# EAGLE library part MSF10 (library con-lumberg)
MSF CONNECTOR
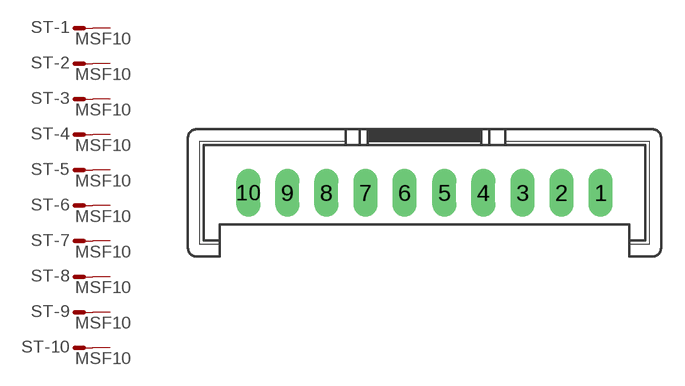
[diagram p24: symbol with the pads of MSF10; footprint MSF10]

Designator prefix ST; gates -1=M -2=M -3=M -4=M -5=M -6=M -7=M -8=M -9=M -10=M

## MSF10 (MPN: 2,5 MSF 10; OC_FARNELL: 1212155; OC_NEWARK: 96K6056)  [MSF10]
1  -1:S  pas
2  -2:S  pas
3  -3:S  pas
4  -4:S  pas
5  -5:S  pas
6  -6:S  pas
7  -7:S  pas
8  -8:S  pas
9  -9:S  pas
10  -10:S  pas

## Footprint MSF10 (pad centres in mm)
MSF CONNECTOR Buerklin Nr. 56 F 562
drill 1.016 long: 1 11.252,-2.54; 2 8.763,-2.54; 3 6.274,-2.54; 4 3.759,-2.54; 5 1.27,-2.54; 6 -1.27,-2.54; 7 -3.759,-2.54; 8 -6.274,-2.54; 9 -8.763,-2.54; 10 -11.252,-2.54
